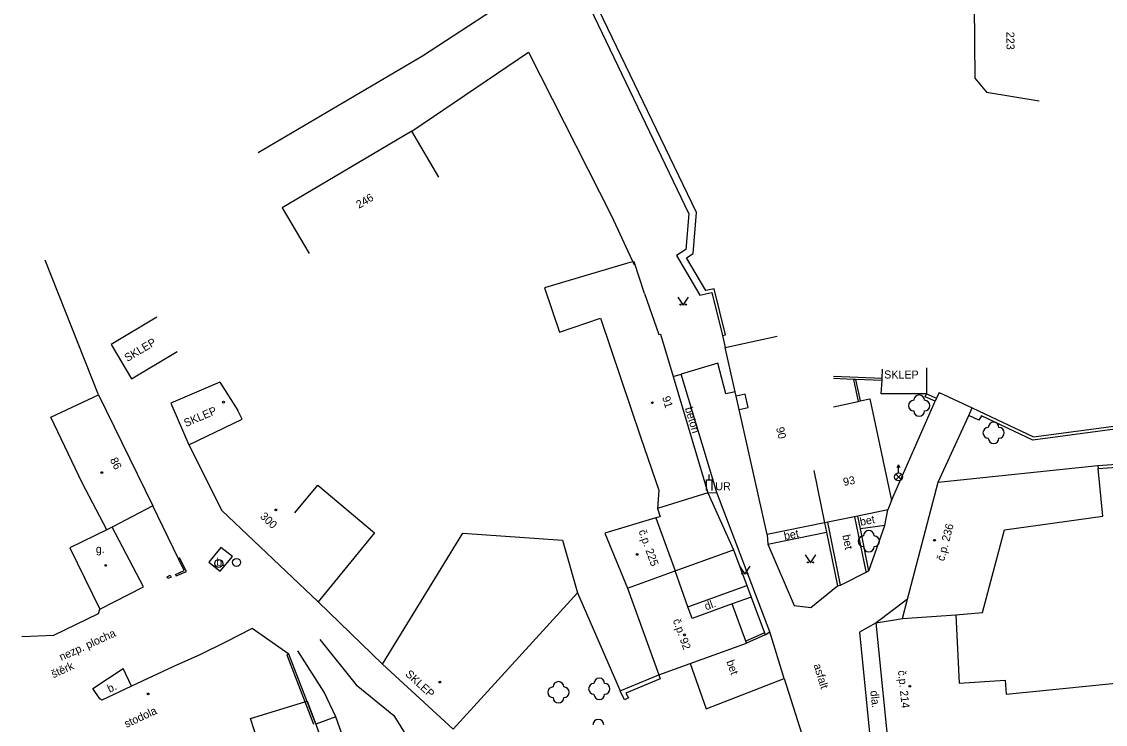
# Model space of a CAD drawing. Extents: x -544674 to -541478, y -1199076 to -1195527.
# Drawn here: x -542684.6 to -542583, y -1198080.6 to -1198014.8 of the extents above; entities that cross this region are included whole.
import ezdxf

# ---------------------------------------------------------------- set-up
doc = ezdxf.new("R2010")
doc.units = 0
for name, color, linetype in [('BUDOVY_MĚŘ', 7, 'Continuous'), ('BUDOVY_NEMĚŘ', 7, 'Continuous'), ('MAP_ZN_BP', 7, 'Continuous'), ('OBVOD_PILÍŘE', 7, 'Continuous'), ('POMOC_POPIS', 7, 'Continuous'), ('ROZHRANÍ_PLOCH', 7, 'Continuous'), ('ZELEŇ', 7, 'Continuous'), ('ZN_BP', 7, 'Continuous'), ('ZN_BUDOV', 7, 'Continuous'), ('ZN_DOPLŇKOVÉ', 7, 'Continuous'), ('ZN_KULTUR', 7, 'Continuous'), ('Č_POPIS_ORIENT', 7, 'Continuous')]:
    doc.layers.add(name, color=color, linetype=linetype)

msp = doc.modelspace()

# ---------------------------------------------------------------- linework, layer by layer
at = {"layer": 'BUDOVY_MĚŘ'}
for points in [[(-542590.35, -1198013.18), (-542595.35, -1198013.25), (-542595.26, -1198020.1), (-542594.19, -1198021.39), (-542589.26, -1198022.2)], [(-542648.03, -1198025.06), (-542660.17, -1198032.23), (-542657.63, -1198036.53)], [(-542645.49, -1198029.37), (-542648.03, -1198025.06)], [(-542626.24, -1198040.27), (-542624.88, -1198044.11), (-542624.74, -1198044.07), (-542623.55, -1198048.04)], [(-542671.92, -1198042.48), (-542676.21, -1198045.04), (-542674.3, -1198048.25), (-542670, -1198045.69)], [(-542618.66, -1198045.34), (-542613.78, -1198044.25)], [(-542617.73, -1198049.47), (-542618.66, -1198045.34)], [(-542603.96, -1198048.23), (-542603.91, -1198047.35)], [(-542599.81, -1198047.22), (-542599.81, -1198049.66)], [(-542623.55, -1198048.04), (-542620.29, -1198058.94)], [(-542599.81, -1198049.66), (-542604.04, -1198049.66), (-542603.97, -1198048.43)], [(-542603.97, -1198048.43), (-542603.96, -1198048.23)], [(-542666.01, -1198048.57), (-542670.61, -1198050.55), (-542668.93, -1198054.45)], [(-542617.64, -1198049.88), (-542617.73, -1198049.47)], [(-542677.39, -1198049.76), (-542672.28, -1198060.17)], [(-542617.36, -1198051.15), (-542616.5, -1198050.96), (-542616.79, -1198049.69), (-542617.64, -1198049.88)], [(-542617.36, -1198051.15), (-542617.64, -1198049.88)], [(-542608.53, -1198050.87), (-542606.21, -1198050.37)], [(-542606.21, -1198050.37), (-542606.01, -1198050.33)], [(-542606.01, -1198050.33), (-542605.12, -1198050.14), (-542603.09, -1198059.67)], [(-542614.74, -1198062.84), (-542617.36, -1198051.15)], [(-542668.93, -1198054.45), (-542665.84, -1198060.6), (-542656.79, -1198069.16)], [(-542598.72, -1198057.93), (-542583.74, -1198056.37)], [(-542583.74, -1198056.37), (-542583.71, -1198056.67)], [(-542610.35, -1198056.85), (-542609.35, -1198061.75)], [(-542601.58, -1198068.91), (-542598.72, -1198057.93)], [(-542620.29, -1198058.94), (-542625, -1198060.42), (-542624.77, -1198061.18), (-542625.16, -1198061.3)], [(-542603.09, -1198059.67), (-542603.42, -1198060.54)], [(-542672.28, -1198060.17), (-542676.09, -1198062.16)], [(-542603.42, -1198060.54), (-542606.24, -1198061.12)], [(-542625.16, -1198061.3), (-542629.94, -1198062.73)], [(-542625.16, -1198061.3), (-542623.36, -1198066.26)], [(-542609.06, -1198061.69), (-542609.35, -1198061.75)], [(-542606.54, -1198061.18), (-542609.06, -1198061.69)], [(-542606.24, -1198061.12), (-542606.54, -1198061.18)], [(-542676.09, -1198062.16), (-542676.6, -1198062.41), (-542680.06, -1198064.1), (-542677.26, -1198069.83), (-542673.18, -1198067.76), (-542676.09, -1198062.16)], [(-542609.35, -1198061.75), (-542614.74, -1198062.84)], [(-542622.15, -1198069.63), (-542623.36, -1198066.26)], [(-542650.76, -1198074.99), (-542644.14, -1198081.09), (-542632.49, -1198068.31)], [(-542627.82, -1198067.87), (-542624.89, -1198075.99)], [(-542618, -1198069.35), (-542621.76, -1198070.71), (-542622.15, -1198069.63)], [(-542616.74, -1198072.83), (-542618, -1198069.35)], [(-542602.06, -1198070.73), (-542601.58, -1198068.91)], [(-542604.52, -1198071.12), (-542602.06, -1198070.73)], [(-542603.16, -1198084.48), (-542604.52, -1198071.12)], [(-542616.67, -1198073.02), (-542616.74, -1198072.83)], [(-542621.94, -1198074.92), (-542616.67, -1198073.02)], [(-542624.89, -1198075.99), (-542621.94, -1198074.92)], [(-542670.42, -1198075.26), (-542674.28, -1198077.06), (-542677.08, -1198078.37)], [(-542657.83, -1198078.48), (-542657.03, -1198080.63)], [(-542657.03, -1198080.63), (-542654.87, -1198086.79), (-542652.02, -1198095.43)]]:
    msp.add_lwpolyline(points, dxfattribs=at)
at = {"layer": 'BUDOVY_NEMĚŘ'}
for points in [[(-542626.24, -1198040.27), (-542627.2, -1198037.31), (-542627.6, -1198037.37), (-542635.59, -1198039.74), (-542634.19, -1198043.89), (-542630.34, -1198042.58), (-542626.56, -1198053.78), (-542624.89, -1198058.7), (-542625, -1198060.42)], [(-542666.01, -1198048.57), (-542664.33, -1198051.22)], [(-542676.6, -1198062.41), (-542678.92, -1198058), (-542681.84, -1198051.84), (-542677.39, -1198049.76)], [(-542668.93, -1198054.45), (-542663.91, -1198052.04), (-542664.33, -1198051.22)], [(-542583.28, -1198061.12), (-542583.71, -1198056.67)], [(-542659, -1198060.83), (-542656.84, -1198058.23)], [(-542656.84, -1198058.23), (-542651.53, -1198062.7)], [(-542592.49, -1198062.41), (-542583.28, -1198061.12)], [(-542651.53, -1198062.7), (-542656.79, -1198069.16)], [(-542650.76, -1198074.99), (-542643.26, -1198062.73), (-542633.92, -1198063.39), (-542632.49, -1198068.31)], [(-542629.94, -1198062.73), (-542627.82, -1198067.87)], [(-542594.54, -1198070.17), (-542592.49, -1198062.41)], [(-542627.82, -1198067.87), (-542623.36, -1198066.26)], [(-542602.06, -1198070.73), (-542597.04, -1198070.39)], [(-542597.04, -1198070.39), (-542594.54, -1198070.17)], [(-542597.04, -1198070.39), (-542596.74, -1198076.77)], [(-542596.74, -1198076.77), (-542592.42, -1198076.51)], [(-542592.42, -1198076.51), (-542592.33, -1198077.8)], [(-542592.33, -1198077.8), (-542579.24, -1198076.5)], [(-542663.14, -1198080.08), (-542658.04, -1198078.54)], [(-542658.04, -1198078.54), (-542657.83, -1198078.48)], [(-542662.93, -1198098.61), (-542664.59, -1198093.18), (-542659.36, -1198091.77), (-542663.14, -1198080.08)]]:
    msp.add_lwpolyline(points, dxfattribs=at)
at = {"layer": 'MAP_ZN_BP'}
for centre, radius in [((-542666.12, -1198065.561), 0.375), ((-542666.12, -1198065.561), 0.0005), ((-542664.45, -1198065.46), 0.375), ((-542664.45, -1198065.46), 0.0005)]:
    msp.add_circle(centre, radius, dxfattribs=at)
at = {"layer": 'OBVOD_PILÍŘE'}
msp.add_lwpolyline([(-542670.67, -1198066.66), (-542670.58, -1198066.83), (-542670.72, -1198066.9), (-542670.87, -1198066.98), (-542670.96, -1198066.81), (-542670.67, -1198066.66)], dxfattribs=at)
at = {"layer": 'ROZHRANÍ_PLOCH'}
for points in [[(-542617.73, -1198049.47), (-542618.59, -1198049.66), (-542619.35, -1198046.78), (-542622.78, -1198047.81)], [(-542623.55, -1198048.04), (-542622.78, -1198047.81)], [(-542619.45, -1198058.92), (-542622.78, -1198047.81)], [(-542603.09, -1198059.67), (-542598.98, -1198050.34)], [(-542598.72, -1198057.93), (-542595.85, -1198051.71)], [(-542620.29, -1198058.94), (-542619.45, -1198058.92)], [(-542614.47, -1198071.98), (-542619.45, -1198058.92)], [(-542603.7, -1198062.01), (-542603.42, -1198060.54)], [(-542614.68, -1198063.76), (-542609.17, -1198062.64)], [(-542603.7, -1198062.01), (-542606, -1198062.31)], [(-542605.2, -1198066.24), (-542603.7, -1198062.01)], [(-542614.74, -1198062.84), (-542614.68, -1198063.76)], [(-542665.91, -1198064.05), (-542667.04, -1198065.44), (-542665.97, -1198066.28), (-542664.84, -1198064.92), (-542665.91, -1198064.05)], [(-542614.68, -1198063.76), (-542612.19, -1198069.5), (-542610.65, -1198069.7), (-542608.15, -1198067.67)], [(-542607.86, -1198067.61), (-542605.2, -1198066.24)], [(-542622.15, -1198069.63), (-542616.65, -1198067.64)], [(-542616.65, -1198067.64), (-542616.23, -1198068.71)], [(-542616.23, -1198068.71), (-542618, -1198069.35)], [(-542601.58, -1198068.91), (-542604.52, -1198071.12)], [(-542604.52, -1198071.12), (-542606.09, -1198072.01), (-542604.84, -1198084.57)], [(-542656.63, -1198072.7), (-542653.23, -1198076.92)], [(-542614.92, -1198072.25), (-542614.47, -1198071.98)], [(-542613.13, -1198076.34), (-542614.47, -1198071.98)], [(-542656.24, -1198077.61), (-542658.69, -1198073.75)], [(-542621.94, -1198074.92), (-542620.45, -1198079.18), (-542613.13, -1198076.34)], [(-542677.08, -1198078.37), (-542677.27, -1198078.25), (-542677.91, -1198077.29), (-542675.06, -1198075.39)], [(-542674.28, -1198077.06), (-542675.06, -1198075.39)], [(-542653.23, -1198076.92), (-542649.71, -1198079.8)], [(-542613.13, -1198076.34), (-542611.28, -1198082.23), (-542611.39, -1198082.9), (-542611.46, -1198083.16)], [(-542655.13, -1198079.92), (-542656.24, -1198077.61)], [(-542655.13, -1198079.92), (-542657.03, -1198080.63)], [(-542652.13, -1198088.5), (-542655.13, -1198079.92)], [(-542649.71, -1198079.8), (-542647.35, -1198083.65)]]:
    msp.add_lwpolyline(points, dxfattribs=at)
at = {"layer": 'ZELEŇ'}
for centre in [(-542600.49, -1198050.77), (-542593.51, -1198053.32), (-542605.21, -1198063.48), (-542634.29, -1198077.63), (-542630.46, -1198077.31)]:
    msp.add_circle(centre, 0.0005, dxfattribs=at)
for centre, start, end in [((-542600.99, -1198050.77), 89.99999, 269.99999), ((-542600.49, -1198050.27), 0, 179.99999), ((-542599.99, -1198050.77), 270, 89.99999), ((-542600.49, -1198051.27), 179.99999, 359.99999), ((-542593.51, -1198052.82), 0, 179.99999), ((-542594.01, -1198053.32), 89.99999, 269.99999), ((-542593.01, -1198053.32), 270, 89.99999), ((-542593.51, -1198053.82), 179.99999, 359.99999), ((-542605.21, -1198062.98), 0, 179.99999), ((-542605.71, -1198063.48), 89.99999, 269.99999), ((-542604.71, -1198063.48), 270, 89.99999), ((-542605.21, -1198063.98), 179.99999, 359.99999), ((-542634.29, -1198077.13), 0, 179.99999), ((-542630.96, -1198077.31), 89.99999, 269.99999), ((-542630.46, -1198076.81), 0, 179.99999), ((-542629.96, -1198077.31), 270, 89.99999), ((-542634.79, -1198077.63), 89.99999, 269.99999), ((-542633.79, -1198077.63), 270, 89.99999), ((-542630.46, -1198077.81), 179.99999, 359.99999), ((-542634.29, -1198078.13), 179.99999, 359.99999), ((-542630.55, -1198080.67), 0, 179.99999)]:
    msp.add_arc(centre, 0.5, start, end, dxfattribs=at)
at = {"layer": 'ZN_BP'}
for p, q in [((-542602.42, -1198057.075), (-542602.42, -1198056.325)), ((-542602.685, -1198057.714), (-542602.156, -1198057.186)), ((-542602.156, -1198057.718), (-542602.685, -1198057.186))]:
    msp.add_line(p, q, dxfattribs=at)
msp.add_lwpolyline([(-542602.545, -1198056.575), (-542602.42, -1198056.325), (-542602.295, -1198056.575)], dxfattribs=at)
msp.add_circle((-542602.42, -1198057.45), 0.375, dxfattribs=at)
at = {"layer": 'ZN_BUDOV'}
for centre in [(-542665.67, -1198050.45), (-542625.49, -1198050.5), (-542677.06, -1198057.05), (-542660.76, -1198060.55), (-542599.05, -1198063.39), (-542626.92, -1198064.71), (-542676.71, -1198065.74), (-542622.49, -1198072.24), (-542645.39, -1198076.67), (-542672.72, -1198077.79), (-542601.36, -1198077.07)]:
    msp.add_circle(centre, 0.0875, dxfattribs=at)
at = {"layer": 'ZN_DOPLŇKOVÉ'}
msp.add_line((-542620.16, -1198057.71), (-542620.16, -1198057.21), dxfattribs=at)
for points in [[(-542618.91, -1198044.21), (-542618.62, -1198044.14), (-542619.69, -1198039.82), (-542620.49, -1198039.98), (-542622.28, -1198036.92), (-542621.68, -1198036.53), (-542621.36, -1198032.68), (-542630.49, -1198013.67), (-542625.77, -1198008.81), (-542615.38, -1197998.11), (-542615.89, -1197997.63), (-542626.27, -1198008.32)], [(-542626.27, -1198008.32), (-542631.33, -1198013.53), (-542622.07, -1198032.81), (-542622.35, -1198036.13), (-542623.22, -1198036.69), (-542621.05, -1198040.41), (-542619.91, -1198040.17), (-542618.91, -1198044.21)], [(-542636.87, -1198011.37), (-542647.04, -1198018.04), (-542662.41, -1198027.08)], [(-542648.03, -1198025.06), (-542637.1, -1198017.65), (-542629.32, -1198032.98), (-542627.19, -1198037.58)], [(-542677.39, -1198049.76), (-542682.39, -1198037.13)], [(-542618.91, -1198044.21), (-542618.66, -1198045.34)], [(-542606.65, -1198048.31), (-542608.53, -1198048.23)], [(-542603.96, -1198048.23), (-542608.52, -1198048.03)], [(-542606.65, -1198048.31), (-542606.21, -1198050.37)], [(-542606.44, -1198048.32), (-542606.65, -1198048.31)], [(-542606.44, -1198048.32), (-542606.01, -1198050.33)], [(-542603.97, -1198048.43), (-542606.44, -1198048.32)], [(-542548.11, -1198048.2), (-542574.23, -1198051.93), (-542589.83, -1198054.02), (-542594.66, -1198051.72), (-542594.9, -1198052.12), (-542595.85, -1198051.71)], [(-542595.52, -1198050.98), (-542589.78, -1198053.71), (-542574.27, -1198051.63), (-542548.15, -1198047.9), (-542548.11, -1198048.2)], [(-542598.61, -1198049.53), (-542598.86, -1198050.07)], [(-542598.61, -1198049.53), (-542595.52, -1198050.98)], [(-542598.98, -1198050.34), (-542599.93, -1198049.94), (-542599.81, -1198049.66)], [(-542599.81, -1198049.66), (-542598.86, -1198050.07)], [(-542598.86, -1198050.07), (-542598.98, -1198050.34)], [(-542595.85, -1198051.71), (-542595.52, -1198050.98)], [(-542583.74, -1198056.37), (-542579.4, -1198056.06)], [(-542583.71, -1198056.67), (-542579.38, -1198056.36), (-542579.4, -1198056.06)], [(-542620.41, -1198058.71), (-542620.41, -1198057.71), (-542619.91, -1198057.71), (-542619.91, -1198058.71)], [(-542620.29, -1198058.94), (-542617.88, -1198064.28)], [(-542669.88, -1198065.12), (-542672.28, -1198060.17)], [(-542607.86, -1198067.61), (-542609.06, -1198061.69)], [(-542606.54, -1198061.18), (-542605.49, -1198066.3), (-542605.2, -1198066.24)], [(-542606, -1198062.31), (-542606.24, -1198061.12)], [(-542609.35, -1198061.75), (-542609.17, -1198062.64)], [(-542609.17, -1198062.64), (-542608.15, -1198067.67)], [(-542605.2, -1198066.24), (-542606, -1198062.31)], [(-542623.36, -1198066.26), (-542617.88, -1198064.28)], [(-542617.88, -1198064.28), (-542616.65, -1198067.64)], [(-542670.17, -1198066.6), (-542669.35, -1198066.21), (-542669.88, -1198065.12)], [(-542670.09, -1198066.72), (-542669.15, -1198066.3), (-542669.78, -1198065.04), (-542669.88, -1198065.12)], [(-542670.17, -1198066.6), (-542670.09, -1198066.72)], [(-542608.15, -1198067.67), (-542607.86, -1198067.61)], [(-542632.49, -1198068.31), (-542628.51, -1198077.5)], [(-542616.23, -1198068.71), (-542614.99, -1198072.06)], [(-542684.58, -1198072.4), (-542681.57, -1198072.27), (-542677.39, -1198070.24), (-542677.26, -1198069.83)], [(-542656.79, -1198069.16), (-542650.76, -1198074.99)], [(-542659.56, -1198074.05), (-542662.97, -1198071.67), (-542665.49, -1198072.93)], [(-542614.99, -1198072.06), (-542616.74, -1198072.83)], [(-542614.92, -1198072.25), (-542616.67, -1198073.02)], [(-542614.99, -1198072.06), (-542614.92, -1198072.25)], [(-542665.49, -1198072.93), (-542667.83, -1198074.08)], [(-542667.83, -1198074.08), (-542670.42, -1198075.26)], [(-542659.56, -1198074.05), (-542659.73, -1198074.13), (-542657.25, -1198080.61)], [(-542657.06, -1198080.54), (-542659.56, -1198074.05)], [(-542627.73, -1198078.15), (-542628.09, -1198078.33), (-542628.51, -1198077.5), (-542624.89, -1198075.99)], [(-542624.89, -1198075.99), (-542624.75, -1198076.37), (-542627.96, -1198077.7), (-542627.73, -1198078.15)]]:
    msp.add_lwpolyline(points, dxfattribs=at)
at = {"layer": 'ZN_KULTUR'}
for points in [[(-542623.1, -1198040.61), (-542622.6, -1198041.36), (-542622.1, -1198040.61)], [(-542611.16, -1198064.76), (-542610.66, -1198065.51), (-542610.16, -1198064.76)], [(-542617.32, -1198065.8), (-542616.82, -1198066.55), (-542616.32, -1198065.8)]]:
    msp.add_lwpolyline(points, dxfattribs=at)
for centre in [(-542622.85, -1198041.31), (-542622.35, -1198041.31), (-542610.91, -1198065.46), (-542610.41, -1198065.46), (-542617.07, -1198066.5), (-542616.57, -1198066.5)]:
    msp.add_circle(centre, 0.05, dxfattribs=at)

# ---------------------------------------------------------------- texts
at = {"layer": 'POMOC_POPIS'}
for s, rotation, p in [('SKLEP', 30.81, (-542674.68, -1198046.69)), ('SKLEP', 359.95002, (-542603.77, -1198048.23)), ('SKLEP', 23.28999, (-542669.19, -1198052.79)), ('beton', 286.66998, (-542622.45, -1198051.02)), ('bet', 11.48998, (-542605.96, -1198062.04)), ('bet', 11.48001, (-542613.08, -1198063.37)), ('bet', 281.48998, (-542607.69, -1198062.93)), ('dl.', 19.89, (-542620.45, -1198069.96)), ('nezp. plocha', 24.48999, (-542680.86, -1198074.71)), ('štěrk', 24.48999, (-542681.6, -1198076.32)), ('bet', 289.36002, (-542618.56, -1198074.75)), ('SKLEP', 317.24238, (-542648.69, -1198076.01)), ('asfalt', 287.45, (-542610.4, -1198075.08)), ('b.', 25.07, (-542676.35, -1198077.68)), ('dla.', 276.44463, (-542605.07, -1198077.51)), ('stodola', 25.03001, (-542674.76, -1198080.98))]:
    msp.add_text(s, height=0.75, rotation=rotation, dxfattribs=at).set_placement(p)
for s, p in [('UR', (-542619.59, -1198058.7)), ('g.', (-542677.63, -1198064.58)), ('b.', (-542666.36, -1198065.79))]:
    msp.add_text(s, height=0.75, dxfattribs=at).set_placement(p)
at = {"layer": 'Č_POPIS_ORIENT'}
for s, rotation, p in [('223', 270.75, (-542592.32, -1198015.75)), ('246', 30.56999, (-542652.97, -1198032.33)), ('91', 286.66998, (-542624.58, -1198050)), ('90', 282.63, (-542613.9, -1198052.86)), ('86', 295.84, (-542676.33, -1198055.84)), ('93', 11.48998, (-542607.53, -1198058.31)), ('300', 316.59001, (-542662.3, -1198061.22)), ('č.p. 225', 289.85001, (-542626.79, -1198062.54)), ('č.p. 236', 75.39999, (-542598.15, -1198065.39)), ('č.p. 92', 289.87001, (-542623.58, -1198070.89)), ('č.p. 214', 275.81002, (-542602.48, -1198075.61))]:
    msp.add_text(s, height=0.75, rotation=rotation, dxfattribs=at).set_placement(p)

doc.saveas('drawing.dxf')
